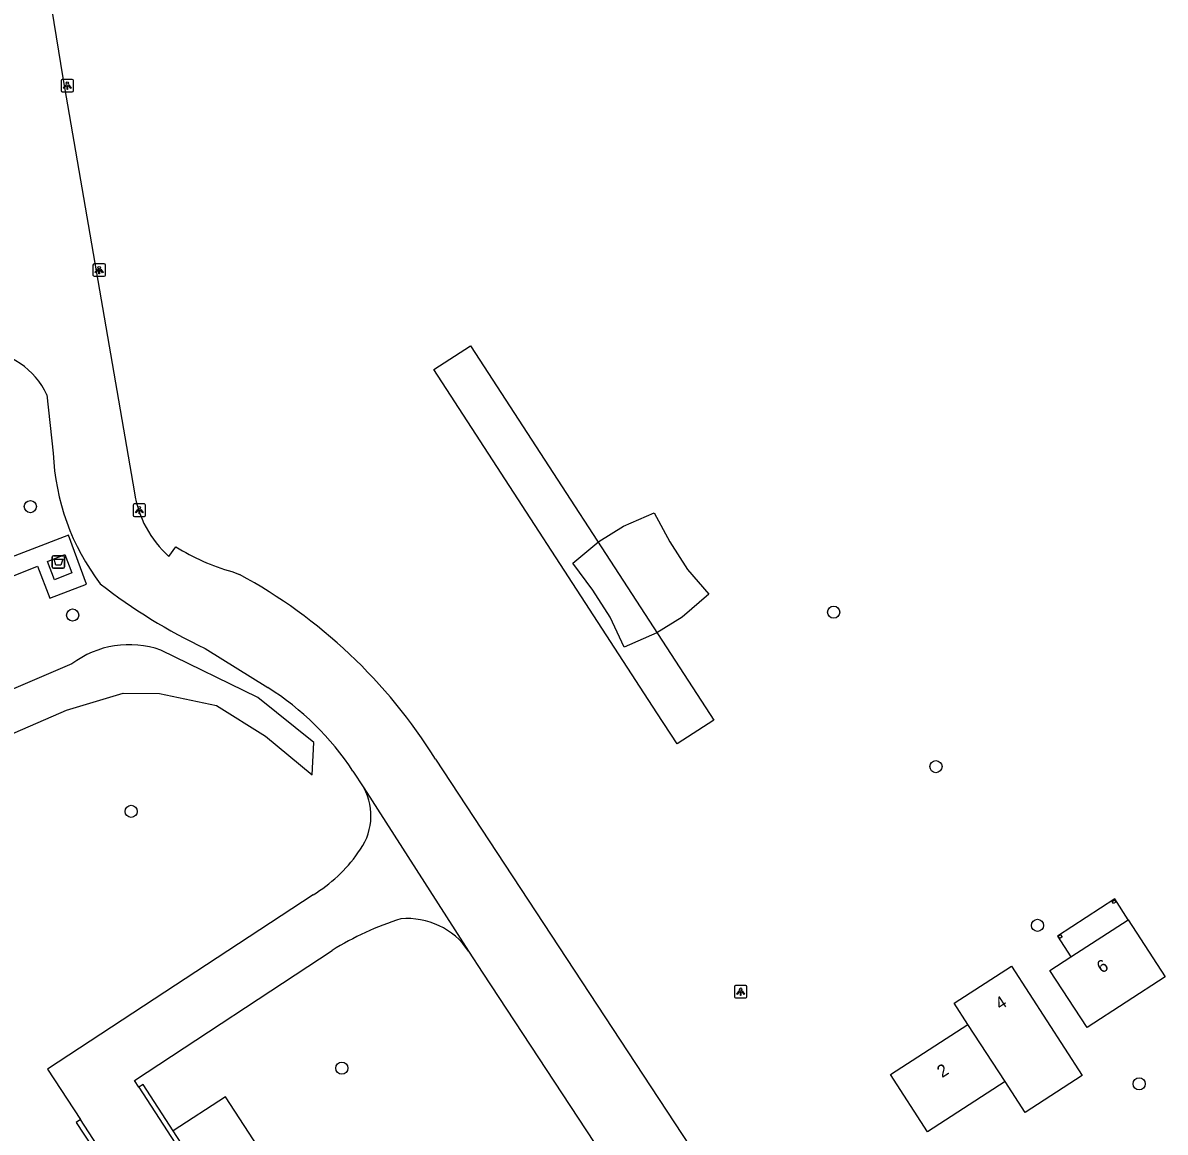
# Model space of a CAD drawing. Extents: x 159451 to 160663, y 388402 to 389723.
# Drawn here: x 159620.6 to 159712.6, y 389199.9 to 389289.3 of the extents above; entities that cross this region are included whole.
import ezdxf

# ---------------------------------------------------------------- set-up
doc = ezdxf.new("R2010")
doc.units = 0
for name, color, linetype in [('IMGEO_Afval_apart_plaats', 7, 'Continuous'), ('IMGEO_Boom', 7, 'Continuous'), ('IMGEO_Lichtpunt', 7, 'Continuous'), ('IMGEO_Meer_plas_ven_vijver', 7, 'Continuous'), ('IMGEO_Pand', 7, 'Continuous'), ('IMGEO_Pand_nummerreeks', 7, 'Continuous'), ('IMGEO_Pand_overbouw', 7, 'Continuous'), ('IMGEO_Pand_vergunning_verleend', 7, 'Continuous'), ('IMGEO_Parkeervlak_halfverhard', 7, 'Continuous'), ('IMGEO_Rijbaan_lokaal_gesloten', 7, 'Continuous'), ('IMGEO_Rijbaan_lokaal_open', 7, 'Continuous'), ('IMGEO_Voetpad_gesloten', 7, 'Continuous'), ('IMGEO_Voetpad_halfverhard', 7, 'Continuous'), ('IMGEO_Voetpad_open', 7, 'Continuous')]:
    doc.layers.add(name, color=color, linetype=linetype)

msp = doc.modelspace()

# ---------------------------------------------------------------- linework, layer by layer
at = {"layer": 'IMGEO_Afval_apart_plaats'}
for p, q in [((159623.066, 389246.372), (159623.856, 389246.372)), ((159623.856, 389246.372), (159623.066, 389246.372)), ((159622.966, 389245.472), (159622.966, 389246.272)), ((159622.966, 389246.272), (159622.966, 389245.472)), ((159623.956, 389246.272), (159623.956, 389245.472)), ((159623.956, 389245.472), (159623.956, 389246.272)), ((159623.856, 389245.372), (159623.066, 389245.372)), ((159623.066, 389245.372), (159623.856, 389245.372))]:
    msp.add_line(p, q, dxfattribs=at)
msp.add_lwpolyline([(159623.109, 389246.086), (159623.813, 389246.086), (159623.664, 389245.616), (159623.258, 389245.616), (159623.109, 389246.086)], dxfattribs=at)
for centre, start, end in [((159623.066, 389246.272), 90, 180), ((159623.066, 389246.272), 90, 180), ((159623.856, 389246.272), 0, 90), ((159623.856, 389246.272), 360, 90), ((159623.066, 389245.472), 180, 270), ((159623.066, 389245.472), 180, 270), ((159623.856, 389245.472), 270, 0), ((159623.856, 389245.472), 270, 0)]:
    msp.add_arc(centre, 0.1, start, end, dxfattribs=at)
at = {"layer": 'IMGEO_Boom'}
for centre in [(159621.204, 389250.328), (159624.61, 389241.591), (159685.893, 389241.819), (159694.126, 389229.381), (159629.32, 389225.777), (159702.309, 389216.594), (159646.282, 389205.086), (159710.493, 389203.831)]:
    msp.add_circle(centre, 0.489, dxfattribs=at)
at = {"layer": 'IMGEO_Lichtpunt'}
for p, q in [((159623.683, 389284.646), (159623.683, 389283.839)), ((159623.683, 389284.646), (159623.683, 389283.839)), ((159624.585, 389284.741), (159623.777, 389284.741)), ((159624.585, 389284.741), (159623.777, 389284.741)), ((159624.679, 389283.839), (159624.679, 389284.646)), ((159624.679, 389283.839), (159624.679, 389284.646)), ((159623.777, 389283.745), (159624.585, 389283.745)), ((159623.777, 389283.745), (159624.585, 389283.745)), ((159626.249, 389269.779), (159626.249, 389268.972)), ((159626.249, 389269.779), (159626.249, 389268.972)), ((159627.151, 389269.874), (159626.343, 389269.874)), ((159627.151, 389269.874), (159626.343, 389269.874)), ((159627.245, 389268.972), (159627.245, 389269.779)), ((159627.245, 389268.972), (159627.245, 389269.779)), ((159626.343, 389268.878), (159627.151, 389268.878)), ((159626.343, 389268.878), (159627.151, 389268.878)), ((159629.484, 389250.443), (159629.484, 389249.636)), ((159629.484, 389250.443), (159629.484, 389249.636)), ((159630.386, 389250.538), (159629.578, 389250.538)), ((159630.386, 389250.538), (159629.578, 389250.538)), ((159630.48, 389249.636), (159630.48, 389250.443)), ((159630.48, 389249.636), (159630.48, 389250.443)), ((159629.578, 389249.542), (159630.386, 389249.542)), ((159629.578, 389249.542), (159630.386, 389249.542)), ((159677.904, 389211.653), (159677.904, 389210.846)), ((159677.904, 389211.653), (159677.904, 389210.846)), ((159678.806, 389211.748), (159677.998, 389211.748)), ((159678.806, 389211.748), (159677.998, 389211.748)), ((159678.9, 389210.846), (159678.9, 389211.653)), ((159678.9, 389210.846), (159678.9, 389211.653)), ((159677.998, 389210.752), (159678.806, 389210.752)), ((159677.998, 389210.752), (159678.806, 389210.752))]:
    msp.add_line(p, q, dxfattribs=at)
for points in [[(159624.057, 389284.31), (159624.096, 389284.282), (159623.908, 389284.02), (159623.87, 389284.047), (159624.057, 389284.31)], [(159624.159, 389284.262), (159624.206, 389284.262), (159624.206, 389283.94), (159624.159, 389283.94), (159624.159, 389284.262)], [(159624.269, 389284.282), (159624.307, 389284.309), (159624.494, 389284.047), (159624.455, 389284.019), (159624.269, 389284.282)], [(159626.623, 389269.443), (159626.662, 389269.415), (159626.474, 389269.153), (159626.436, 389269.18), (159626.623, 389269.443)], [(159626.725, 389269.395), (159626.772, 389269.395), (159626.772, 389269.073), (159626.725, 389269.073), (159626.725, 389269.395)], [(159626.835, 389269.415), (159626.873, 389269.442), (159627.06, 389269.18), (159627.021, 389269.152), (159626.835, 389269.415)], [(159629.858, 389250.107), (159629.897, 389250.079), (159629.709, 389249.817), (159629.671, 389249.844), (159629.858, 389250.107)], [(159629.96, 389250.059), (159630.007, 389250.059), (159630.007, 389249.737), (159629.96, 389249.737), (159629.96, 389250.059)], [(159630.07, 389250.079), (159630.108, 389250.106), (159630.295, 389249.844), (159630.256, 389249.816), (159630.07, 389250.079)], [(159678.278, 389211.317), (159678.317, 389211.289), (159678.129, 389211.027), (159678.091, 389211.054), (159678.278, 389211.317)], [(159678.38, 389211.269), (159678.427, 389211.269), (159678.427, 389210.947), (159678.38, 389210.947), (159678.38, 389211.269)], [(159678.49, 389211.289), (159678.528, 389211.316), (159678.715, 389211.054), (159678.676, 389211.026), (159678.49, 389211.289)]]:
    msp.add_lwpolyline(points, dxfattribs=at)
for centre in [(159624.182, 389284.444), (159626.748, 389269.577), (159629.983, 389250.241), (159678.403, 389211.451)]:
    msp.add_circle(centre, 0.0994, dxfattribs=at)
for centre, start, end in [((159623.777, 389284.646), 90, 180), ((159623.777, 389284.646), 90, 180), ((159624.585, 389284.646), 0, 90), ((159624.585, 389284.646), 0, 90), ((159623.777, 389283.839), 180, 270), ((159623.777, 389283.839), 180, 270), ((159624.585, 389283.839), 270, 0), ((159624.585, 389283.839), 270, 360), ((159626.343, 389269.779), 90, 180), ((159626.343, 389269.779), 90, 180), ((159627.151, 389269.779), 0, 90), ((159627.151, 389269.779), 0, 90), ((159626.343, 389268.972), 180, 270), ((159626.343, 389268.972), 180, 270), ((159627.151, 389268.972), 270, 0), ((159627.151, 389268.972), 270, 360), ((159629.578, 389250.443), 90, 180), ((159629.578, 389250.443), 90, 180), ((159630.386, 389250.443), 0, 90), ((159630.386, 389250.443), 0, 90), ((159629.578, 389249.636), 180, 270), ((159629.578, 389249.636), 180, 270), ((159630.386, 389249.636), 270, 0), ((159630.386, 389249.636), 270, 360), ((159677.998, 389211.653), 90, 180), ((159677.998, 389211.653), 90, 180), ((159678.806, 389211.653), 0, 90), ((159678.806, 389211.653), 0, 90), ((159677.998, 389210.846), 180, 270), ((159677.998, 389210.846), 180, 270), ((159678.806, 389210.846), 270, 0), ((159678.806, 389210.846), 270, 360)]:
    msp.add_arc(centre, 0.0946, start, end, dxfattribs=at)
at = {"layer": 'IMGEO_Meer_plas_ven_vijver'}
for points in [[(159624.547, 389237.657), (159612.306, 389232.426), (159600.984, 389227.884), (159599.817, 389228.1), (159593.954, 389242.412), (159589.472, 389255.292)], [(159599.482, 389221.913), (159600.652, 389222.595), (159602.698, 389224.956), (159611.489, 389228.443), (159624.11, 389233.935), (159628.679, 389235.295), (159631.61, 389235.275), (159636.202, 389234.295), (159640.145, 389231.846), (159643.886, 389228.729), (159644.026, 389231.331), (159639.518, 389234.95), (159631.712, 389238.772)]]:
    msp.add_lwpolyline(points, dxfattribs=at)
msp.add_arc((159629.167, 389231.547), 7.66, 70.59532, 127.09525, dxfattribs=at)
at = {"layer": 'IMGEO_Pand'}
for points in [[(159708.497, 389218.649), (159708.617, 389218.464), (159708.432, 389218.345), (159708.313, 389218.529), (159708.497, 389218.649)], [(159709.602, 389217.049), (159712.584, 389212.435), (159706.305, 389208.362), (159703.303, 389212.96), (159704.993, 389214.057), (159709.602, 389217.049)], [(159704.165, 389215.844), (159704.285, 389215.66), (159704.1, 389215.54), (159703.981, 389215.725), (159704.165, 389215.844)], [(159696.704, 389208.604), (159695.596, 389210.321), (159700.208, 389213.306), (159705.909, 389204.513), (159701.308, 389201.523), (159699.696, 389204.011)], [(159699.696, 389204.011), (159693.447, 389199.961), (159690.467, 389204.568), (159696.704, 389208.604)], [(159699.696, 389204.011), (159696.704, 389208.604)]]:
    msp.add_lwpolyline(points, dxfattribs=at)
at = {"layer": 'IMGEO_Pand_overbouw'}
msp.add_lwpolyline([(159709.602, 389217.049), (159708.523, 389218.718), (159703.915, 389215.735), (159704.993, 389214.057)], close=True, dxfattribs=at)
at = {"layer": 'IMGEO_Pand_vergunning_verleend'}
msp.add_lwpolyline([(159664.895, 389245.775), (159666.968, 389247.521), (159668.968, 389248.746), (159671.429, 389249.825), (159672.706, 389247.479), (159674.119, 389245.252), (159675.827, 389243.268), (159673.687, 389241.424), (159671.644, 389240.149), (159669.018, 389239.013), (159667.896, 389241.431), (159666.507, 389243.604), (159664.895, 389245.775)], dxfattribs=at)
at = {"layer": 'IMGEO_Parkeervlak_halfverhard'}
msp.add_lwpolyline([(159642.459, 389184.995), (159646.699, 389187.782), (159636.923, 389202.786), (159632.7, 389200.044)], dxfattribs=at)
at = {"layer": 'IMGEO_Rijbaan_lokaal_gesloten'}
for points in [[(159620.983, 389304.296), (159621.487, 389299.27), (159623.828, 389284.864), (159629.586, 389251.444)], [(159622.533, 389259.327), (159623.046, 389254.626)], [(159632.346, 389246.313), (159632.915, 389247.094)], [(159637.438, 389245.095), (159638.056, 389244.853)], [(159635.284, 389238.901), (159640.333, 389235.75)], [(159653.827, 389229.979), (159689.805, 389175.234)], [(159647.183, 389229.023), (159648.051, 389227.67)], [(159648.051, 389227.67), (159656.489, 389214.521)], [(159643.969, 389219.053), (159622.589, 389205.016), (159625.23, 389200.952)], [(159629.935, 389203.561), (159629.59, 389204.095), (159645.504, 389214.571)], [(159656.489, 389214.521), (159657.638, 389212.73), (159685.775, 389169.94), (159691.273, 389160.827)], [(159629.935, 389203.561), (159653.451, 389167.32), (159648.981, 389164.401), (159625.23, 389200.952)]]:
    msp.add_lwpolyline(points, dxfattribs=at)
for centre, radius, start, end in [((159616.857, 389256.687), 6.26, 24.93997, 86.38805), ((159641.688, 389255.396), 18.658, 182.36635, 217.23295), ((159638.185, 389252.762), 8.699, 188.71174, 227.84048), ((159642.113, 389261.788), 17.335, 237.95633, 254.35634), ((159617.866, 389207.647), 42.331, 31.84029, 61.51293), ((159654.684, 389279.856), 45.318, 232.07875, 244.6533), ((159628.065, 389216.406), 22.906, 33.42198, 57.61612), ((159643.889, 389225.407), 4.738, 321.28022, 28.52866), ((159637.888, 389229.161), 11.796, 301.03155, 325.29009), ((159658.268, 389194.137), 24.093, 107.45688, 121.98966), ((159651.564, 389211.207), 5.936, 33.93814, 95.06254)]:
    msp.add_arc(centre, radius, start, end, dxfattribs=at)
at = {"layer": 'IMGEO_Rijbaan_lokaal_open'}
for points in [[(159632.7, 389200.044), (159630.302, 389203.784), (159629.935, 389203.561)], [(159625.23, 389200.952), (159624.888, 389200.722), (159627.533, 389196.703)], [(159642.459, 389184.995), (159632.7, 389200.044)]]:
    msp.add_lwpolyline(points, dxfattribs=at)
at = {"layer": 'IMGEO_Voetpad_gesloten'}
msp.add_lwpolyline([(159622.595, 389245.917), (159623.989, 389246.466), (159624.545, 389244.979), (159623.153, 389244.439), (159622.595, 389245.917)], dxfattribs=at)
at = {"layer": 'IMGEO_Voetpad_halfverhard'}
msp.add_lwpolyline([(159616.727, 389243.514), (159621.787, 389245.516), (159622.78, 389242.945), (159625.725, 389244.071), (159624.267, 389248.016), (159611.506, 389243.126)], dxfattribs=at)
at = {"layer": 'IMGEO_Voetpad_open'}
msp.add_lwpolyline([(159674.55, 389235.721), (159676.242, 389233.117), (159673.28, 389231.215), (159671.661, 389233.706), (159653.682, 389261.36), (159656.655, 389263.269), (159674.55, 389235.721)], dxfattribs=at)

# ---------------------------------------------------------------- texts
at = {"layer": 'IMGEO_Pand_nummerreeks'}
for s, rotation, p in [('6', 32.99091, (159707.485, 389212.694)), ('4', 32.9107, (159699.308, 389209.745)), ('2', 32.90497, (159694.624, 389204.28))]:
    msp.add_text(s, height=1, rotation=rotation, dxfattribs=at).set_placement(p)

doc.saveas('drawing.dxf')
